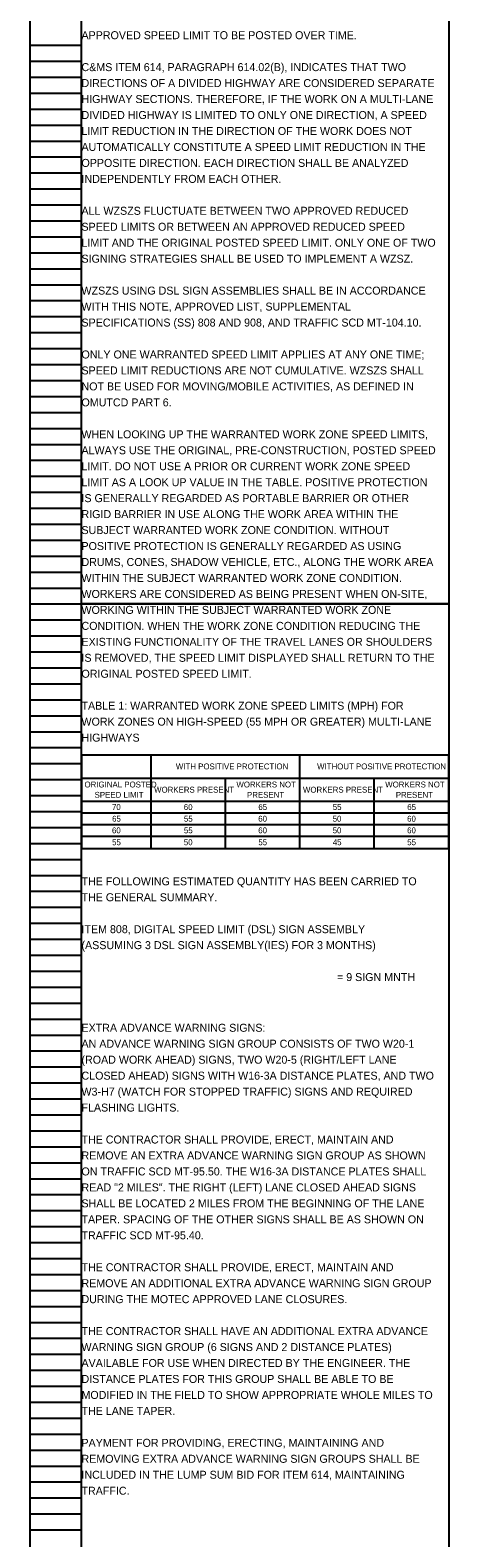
# Model space of a CAD drawing. Extents: x 16463 to 16500, y 5400 to 5823.
# Drawn here: x 16463.05 to 16470.39, y 5585.33 to 5611.78 of the extents above; entities that cross this region are included whole.
import ezdxf

# ---------------------------------------------------------------- set-up
doc = ezdxf.new("R2010")
doc.units = 0
for name, color, linetype in [('Default', 7, 'Continuous'), ('SC_Scratch1', 7, 'Continuous'), ('SH_Data', 7, 'Continuous')]:
    doc.layers.add(name, color=color, linetype=linetype)

msp = doc.modelspace()

# ---------------------------------------------------------------- linework, layer by layer
at = {"layer": 'Default'}
for p, q in [((16463.949, 5599.067), (16470.382, 5599.067)), ((16463.949, 5599.067), (16463.949, 5597.425)), ((16465.163, 5599.067), (16465.163, 5597.425)), ((16467.772, 5599.067), (16467.772, 5597.425)), ((16470.382, 5599.067), (16470.382, 5597.425)), ((16463.949, 5598.659), (16470.382, 5598.659)), ((16466.467, 5598.659), (16466.467, 5597.425)), ((16469.077, 5598.659), (16469.077, 5597.425)), ((16463.949, 5598.251), (16470.382, 5598.251)), ((16463.949, 5598.047), (16470.382, 5598.047)), ((16463.949, 5597.843), (16470.382, 5597.843)), ((16463.949, 5597.64), (16470.382, 5597.64)), ((16463.949, 5597.425), (16470.382, 5597.425))]:
    msp.add_line(p, q, dxfattribs=at)
at = {"layer": 'SC_Scratch1'}
for points in [[(16463.949, 5621.872), (16470.389, 5621.872), (16470.389, 5601.712), (16463.949, 5601.712)], [(16463.949, 5601.712), (16470.389, 5601.712), (16470.389, 5581.552), (16463.949, 5581.552)]]:
    msp.add_lwpolyline(points, close=True, dxfattribs=at)
at = {"layer": 'SH_Data'}
for p, q in [((16463.049, 5601.712), (16463.049, 5621.872)), ((16463.949, 5601.712), (16463.949, 5621.872)), ((16463.049, 5611.512), (16463.949, 5611.512)), ((16463.049, 5611.232), (16463.949, 5611.232)), ((16463.049, 5610.952), (16463.949, 5610.952)), ((16463.049, 5610.672), (16463.949, 5610.672)), ((16463.049, 5610.392), (16463.949, 5610.392)), ((16463.049, 5610.112), (16463.949, 5610.112)), ((16463.049, 5609.832), (16463.949, 5609.832)), ((16463.049, 5609.552), (16463.949, 5609.552)), ((16463.049, 5609.272), (16463.949, 5609.272)), ((16463.049, 5608.992), (16463.949, 5608.992)), ((16463.049, 5608.712), (16463.949, 5608.712)), ((16463.049, 5608.432), (16463.949, 5608.432)), ((16463.049, 5608.152), (16463.949, 5608.152)), ((16463.049, 5607.872), (16463.949, 5607.872)), ((16463.049, 5607.592), (16463.949, 5607.592)), ((16463.049, 5607.312), (16463.949, 5607.312)), ((16463.049, 5607.032), (16463.949, 5607.032)), ((16463.049, 5606.752), (16463.949, 5606.752)), ((16463.049, 5606.472), (16463.949, 5606.472)), ((16463.049, 5606.192), (16463.949, 5606.192)), ((16463.049, 5605.912), (16463.949, 5605.912)), ((16463.049, 5605.632), (16463.949, 5605.632)), ((16463.049, 5605.352), (16463.949, 5605.352)), ((16463.049, 5605.072), (16463.949, 5605.072)), ((16463.049, 5604.792), (16463.949, 5604.792)), ((16463.049, 5604.512), (16463.949, 5604.512)), ((16463.049, 5604.232), (16463.949, 5604.232)), ((16463.049, 5603.952), (16463.949, 5603.952)), ((16463.049, 5603.672), (16463.949, 5603.672)), ((16463.049, 5603.392), (16463.949, 5603.392)), ((16463.049, 5603.112), (16463.949, 5603.112)), ((16463.049, 5602.832), (16463.949, 5602.832)), ((16463.049, 5602.552), (16463.949, 5602.552)), ((16463.049, 5602.272), (16463.949, 5602.272)), ((16463.049, 5601.992), (16463.949, 5601.992)), ((16463.049, 5581.552), (16463.049, 5601.712)), ((16463.049, 5601.712), (16463.949, 5601.712)), ((16463.049, 5601.712), (16463.949, 5601.712)), ((16463.949, 5581.552), (16463.949, 5601.712)), ((16463.049, 5601.432), (16463.949, 5601.432)), ((16463.049, 5601.152), (16463.949, 5601.152)), ((16463.049, 5600.872), (16463.949, 5600.872)), ((16463.049, 5600.592), (16463.949, 5600.592)), ((16463.049, 5600.312), (16463.949, 5600.312)), ((16463.049, 5600.032), (16463.949, 5600.032)), ((16463.049, 5599.752), (16463.949, 5599.752)), ((16463.049, 5599.472), (16463.949, 5599.472)), ((16463.049, 5599.192), (16463.949, 5599.192)), ((16463.049, 5598.912), (16463.949, 5598.912)), ((16463.049, 5598.632), (16463.949, 5598.632)), ((16463.049, 5598.352), (16463.949, 5598.352)), ((16463.049, 5598.072), (16463.949, 5598.072)), ((16463.049, 5597.792), (16463.949, 5597.792)), ((16463.049, 5597.512), (16463.949, 5597.512)), ((16463.049, 5597.232), (16463.949, 5597.232)), ((16463.049, 5596.952), (16463.949, 5596.952)), ((16463.049, 5596.672), (16463.949, 5596.672)), ((16463.049, 5596.392), (16463.949, 5596.392)), ((16463.049, 5596.112), (16463.949, 5596.112)), ((16463.049, 5595.832), (16463.949, 5595.832)), ((16463.049, 5595.552), (16463.949, 5595.552)), ((16463.049, 5595.272), (16463.949, 5595.272)), ((16463.049, 5594.992), (16463.949, 5594.992)), ((16463.049, 5594.712), (16463.949, 5594.712)), ((16463.049, 5594.432), (16463.949, 5594.432)), ((16463.049, 5594.152), (16463.949, 5594.152)), ((16463.049, 5593.872), (16463.949, 5593.872)), ((16463.049, 5593.592), (16463.949, 5593.592)), ((16463.049, 5593.312), (16463.949, 5593.312)), ((16463.049, 5593.032), (16463.949, 5593.032)), ((16463.049, 5592.752), (16463.949, 5592.752)), ((16463.049, 5592.472), (16463.949, 5592.472)), ((16463.049, 5592.192), (16463.949, 5592.192)), ((16463.049, 5591.912), (16463.949, 5591.912)), ((16463.049, 5591.632), (16463.949, 5591.632)), ((16463.049, 5591.352), (16463.949, 5591.352)), ((16463.049, 5591.072), (16463.949, 5591.072)), ((16463.049, 5590.792), (16463.949, 5590.792)), ((16463.049, 5590.512), (16463.949, 5590.512)), ((16463.049, 5590.232), (16463.949, 5590.232)), ((16463.049, 5589.952), (16463.949, 5589.952)), ((16463.049, 5589.672), (16463.949, 5589.672)), ((16463.049, 5589.392), (16463.949, 5589.392)), ((16463.049, 5589.112), (16463.949, 5589.112)), ((16463.049, 5588.832), (16463.949, 5588.832)), ((16463.049, 5588.552), (16463.949, 5588.552)), ((16463.049, 5588.272), (16463.949, 5588.272)), ((16463.049, 5587.992), (16463.949, 5587.992)), ((16463.049, 5587.712), (16463.949, 5587.712)), ((16463.049, 5587.432), (16463.949, 5587.432)), ((16463.049, 5587.152), (16463.949, 5587.152)), ((16463.049, 5586.872), (16463.949, 5586.872)), ((16463.049, 5586.592), (16463.949, 5586.592)), ((16463.049, 5586.312), (16463.949, 5586.312)), ((16463.049, 5586.032), (16463.949, 5586.032)), ((16463.049, 5585.752), (16463.949, 5585.752)), ((16463.049, 5585.472), (16463.949, 5585.472))]:
    msp.add_line(p, q, dxfattribs=at)

# ---------------------------------------------------------------- texts
at = {"layer": 'Default'}
for s, height, p in [('APPROVED SPEED LIMIT TO BE POSTED OVER TIME. ', 0.14, (16463.949, 5611.618)), ('C&MS ITEM 614, PARAGRAPH 614.02(B), INDICATES THAT TWO ', 0.14, (16463.949, 5611.058)), ('DIRECTIONS OF A DIVIDED HIGHWAY ARE CONSIDERED SEPARATE ', 0.14, (16463.949, 5610.778)), ('HIGHWAY SECTIONS. THEREFORE, IF THE WORK ON A MULTI-LANE ', 0.14, (16463.949, 5610.498)), ('DIVIDED HIGHWAY IS LIMITED TO ONLY ONE DIRECTION, A SPEED ', 0.14, (16463.949, 5610.218)), ('LIMIT REDUCTION IN THE DIRECTION OF THE WORK DOES NOT ', 0.14, (16463.949, 5609.938)), ('AUTOMATICALLY CONSTITUTE A SPEED LIMIT REDUCTION IN THE ', 0.14, (16463.949, 5609.658)), ('OPPOSITE DIRECTION. EACH DIRECTION SHALL BE ANALYZED ', 0.14, (16463.949, 5609.378)), ('INDEPENDENTLY FROM EACH OTHER. ', 0.14, (16463.949, 5609.098)), ('ALL WZSZS FLUCTUATE BETWEEN TWO APPROVED REDUCED ', 0.14, (16463.949, 5608.538)), ('SPEED LIMITS OR BETWEEN AN APPROVED REDUCED SPEED ', 0.14, (16463.949, 5608.258)), ('LIMIT AND THE ORIGINAL POSTED SPEED LIMIT. ONLY ONE OF TWO ', 0.14, (16463.949, 5607.978)), ('SIGNING STRATEGIES SHALL BE USED TO IMPLEMENT A WZSZ.', 0.14, (16463.949, 5607.698)), ('WZSZS USING DSL SIGN ASSEMBLIES SHALL BE IN ACCORDANCE ', 0.14, (16463.949, 5607.138)), ('WITH THIS NOTE, APPROVED LIST, SUPPLEMENTAL ', 0.14, (16463.949, 5606.858)), ('SPECIFICATIONS (SS) 808 AND 908, AND TRAFFIC SCD MT-104.10.', 0.14, (16463.949, 5606.578)), ('ONLY ONE WARRANTED SPEED LIMIT APPLIES AT ANY ONE TIME; ', 0.14, (16463.949, 5606.018)), ('SPEED LIMIT REDUCTIONS ARE NOT CUMULATIVE. WZSZS SHALL ', 0.14, (16463.949, 5605.738)), ('NOT BE USED FOR MOVING/MOBILE ACTIVITIES, AS DEFINED IN ', 0.14, (16463.949, 5605.458)), ('OMUTCD PART 6.', 0.14, (16463.949, 5605.178)), ('WHEN LOOKING UP THE WARRANTED WORK ZONE SPEED LIMITS, ', 0.14, (16463.949, 5604.618)), ('ALWAYS USE THE ORIGINAL, PRE-CONSTRUCTION, POSTED SPEED ', 0.14, (16463.949, 5604.338)), ('LIMIT. DO NOT USE A PRIOR OR CURRENT WORK ZONE SPEED ', 0.14, (16463.949, 5604.058)), ('LIMIT AS A LOOK UP VALUE IN THE TABLE. POSITIVE PROTECTION ', 0.14, (16463.949, 5603.778)), ('IS GENERALLY REGARDED AS PORTABLE BARRIER OR OTHER ', 0.14, (16463.949, 5603.498)), ('RIGID BARRIER IN USE ALONG THE WORK AREA WITHIN THE ', 0.14, (16463.949, 5603.218)), ('SUBJECT WARRANTED WORK ZONE CONDITION. WITHOUT ', 0.14, (16463.949, 5602.938)), ('POSITIVE PROTECTION IS GENERALLY REGARDED AS USING ', 0.14, (16463.949, 5602.658)), ('DRUMS, CONES, SHADOW VEHICLE, ETC., ALONG THE WORK AREA ', 0.14, (16463.949, 5602.378)), ('WITHIN THE SUBJECT WARRANTED WORK ZONE CONDITION. ', 0.14, (16463.949, 5602.098)), ('WORKERS ARE CONSIDERED AS BEING PRESENT WHEN ON-SITE, ', 0.14, (16463.949, 5601.818)), ('WORKING WITHIN THE SUBJECT WARRANTED WORK ZONE ', 0.14, (16463.949, 5601.538)), ('CONDITION. WHEN THE WORK ZONE CONDITION REDUCING THE ', 0.14, (16463.949, 5601.258)), ('EXISTING FUNCTIONALITY OF THE TRAVEL LANES OR SHOULDERS ', 0.14, (16463.949, 5600.978)), ('IS REMOVED, THE SPEED LIMIT DISPLAYED SHALL RETURN TO THE ', 0.14, (16463.949, 5600.698)), ('ORIGINAL POSTED SPEED LIMIT. ', 0.14, (16463.949, 5600.418)), ('TABLE 1: WARRANTED WORK ZONE SPEED LIMITS (MPH) FOR ', 0.14, (16463.949, 5599.858)), ('WORK ZONES ON HIGH-SPEED (55 MPH OR GREATER) MULTI-LANE ', 0.14, (16463.949, 5599.578)), ('HIGHWAYS', 0.14, (16463.949, 5599.298)), ('WITH POSITIVE PROTECTION', 0.10317, (16465.604, 5598.811)), ('WITHOUT POSITIVE PROTECTION', 0.10317, (16468.08, 5598.811)), ('ORIGINAL POSTED ', 0.10317, (16464.002, 5598.494)), ('WORKERS PRESENT', 0.10317, (16465.222, 5598.403)), ('WORKERS NOT ', 0.10317, (16466.665, 5598.494)), ('WORKERS PRESENT', 0.10317, (16467.832, 5598.403)), ('WORKERS NOT ', 0.10317, (16469.274, 5598.494)), ('SPEED LIMIT', 0.10317, (16464.179, 5598.313)), ('70', 0.1032, (16464.484, 5598.098)), ('60', 0.1032, (16465.743, 5598.098)), ('PRESENT', 0.1032, (16466.851, 5598.313)), ('65', 0.1032, (16467.05, 5598.098)), ('55', 0.1032, (16468.355, 5598.098)), ('PRESENT', 0.1032, (16469.46, 5598.313)), ('65', 0.1032, (16469.66, 5598.098)), ('65', 0.1032, (16464.486, 5597.894)), ('55', 0.1032, (16465.745, 5597.894)), ('60', 0.1032, (16467.048, 5597.894)), ('50', 0.1032, (16468.353, 5597.894)), ('60', 0.1032, (16469.658, 5597.894)), ('60', 0.1032, (16464.484, 5597.69)), ('55', 0.1032, (16465.745, 5597.69)), ('60', 0.1032, (16467.048, 5597.69)), ('50', 0.1032, (16468.353, 5597.69)), ('60', 0.1032, (16469.658, 5597.69)), ('55', 0.1032, (16464.486, 5597.481)), ('50', 0.1032, (16465.743, 5597.481)), ('55', 0.1032, (16467.05, 5597.481)), ('45', 0.1032, (16468.355, 5597.481)), ('55', 0.1032, (16469.66, 5597.481)), ('THE FOLLOWING ESTIMATED QUANTITY HAS BEEN CARRIED TO ', 0.14, (16463.949, 5596.778)), ('THE GENERAL SUMMARY.', 0.14, (16463.949, 5596.498)), ('ITEM 808, DIGITAL SPEED LIMIT (DSL) SIGN ASSEMBLY ', 0.14, (16463.949, 5595.938)), ('(ASSUMING 3 DSL SIGN ASSEMBLY(IES) FOR 3 MONTHS)', 0.14, (16463.949, 5595.658)), ('= 9 SIGN MNTH', 0.14, (16468.429, 5595.098)), ('EXTRA ADVANCE WARNING SIGNS:', 0.14, (16463.949, 5594.209)), ('AN ADVANCE WARNING SIGN GROUP CONSISTS OF TWO W20-1 ', 0.14, (16463.949, 5593.929)), ('(ROAD WORK AHEAD) SIGNS, TWO W20-5 (RIGHT/LEFT LANE ', 0.14, (16463.949, 5593.649)), ('CLOSED AHEAD) SIGNS WITH W16-3A DISTANCE PLATES, AND TWO ', 0.14, (16463.949, 5593.369)), ('W3-H7 (WATCH FOR STOPPED TRAFFIC) SIGNS AND REQUIRED ', 0.14, (16463.949, 5593.089)), ('FLASHING LIGHTS. ', 0.14, (16463.949, 5592.809)), ('THE CONTRACTOR SHALL PROVIDE, ERECT, MAINTAIN AND ', 0.14, (16463.949, 5592.249)), ('REMOVE AN EXTRA ADVANCE WARNING SIGN GROUP AS SHOWN ', 0.14, (16463.949, 5591.969)), ('ON TRAFFIC SCD MT-95.50. THE W16-3A DISTANCE PLATES SHALL ', 0.14, (16463.949, 5591.689)), ('READ "2 MILES". THE RIGHT (LEFT) LANE CLOSED AHEAD SIGNS ', 0.14, (16463.949, 5591.409)), ('SHALL BE LOCATED 2 MILES FROM THE BEGINNING OF THE LANE ', 0.14, (16463.949, 5591.129)), ('TAPER. SPACING OF THE OTHER SIGNS SHALL BE AS SHOWN ON ', 0.14, (16463.949, 5590.849)), ('TRAFFIC SCD MT-95.40. ', 0.14, (16463.949, 5590.569)), ('THE CONTRACTOR SHALL PROVIDE, ERECT, MAINTAIN AND ', 0.14, (16463.949, 5590.009)), ('REMOVE AN ADDITIONAL EXTRA ADVANCE WARNING SIGN GROUP ', 0.14, (16463.949, 5589.729)), ('DURING THE MOTEC APPROVED LANE CLOSURES.', 0.14, (16463.949, 5589.449)), ('THE CONTRACTOR SHALL HAVE AN ADDITIONAL EXTRA ADVANCE ', 0.14, (16463.949, 5588.889)), ('WARNING SIGN GROUP (6 SIGNS AND 2 DISTANCE PLATES) ', 0.14, (16463.949, 5588.609)), ('AVAILABLE FOR USE WHEN DIRECTED BY THE ENGINEER. THE ', 0.14, (16463.949, 5588.329)), ('DISTANCE PLATES FOR THIS GROUP SHALL BE ABLE TO BE ', 0.14, (16463.949, 5588.049)), ('MODIFIED IN THE FIELD TO SHOW APPROPRIATE WHOLE MILES TO ', 0.14, (16463.949, 5587.769)), ('THE LANE TAPER.', 0.14, (16463.949, 5587.489)), ('PAYMENT FOR PROVIDING, ERECTING, MAINTAINING AND ', 0.14, (16463.949, 5586.929)), ('REMOVING EXTRA ADVANCE WARNING SIGN GROUPS SHALL BE ', 0.14, (16463.949, 5586.649)), ('INCLUDED IN THE LUMP SUM BID FOR ITEM 614, MAINTAINING ', 0.14, (16463.949, 5586.369)), ('TRAFFIC.', 0.14, (16463.949, 5586.089))]:
    msp.add_text(s, height=height, dxfattribs=at).set_placement(p)

doc.saveas('drawing.dxf')
